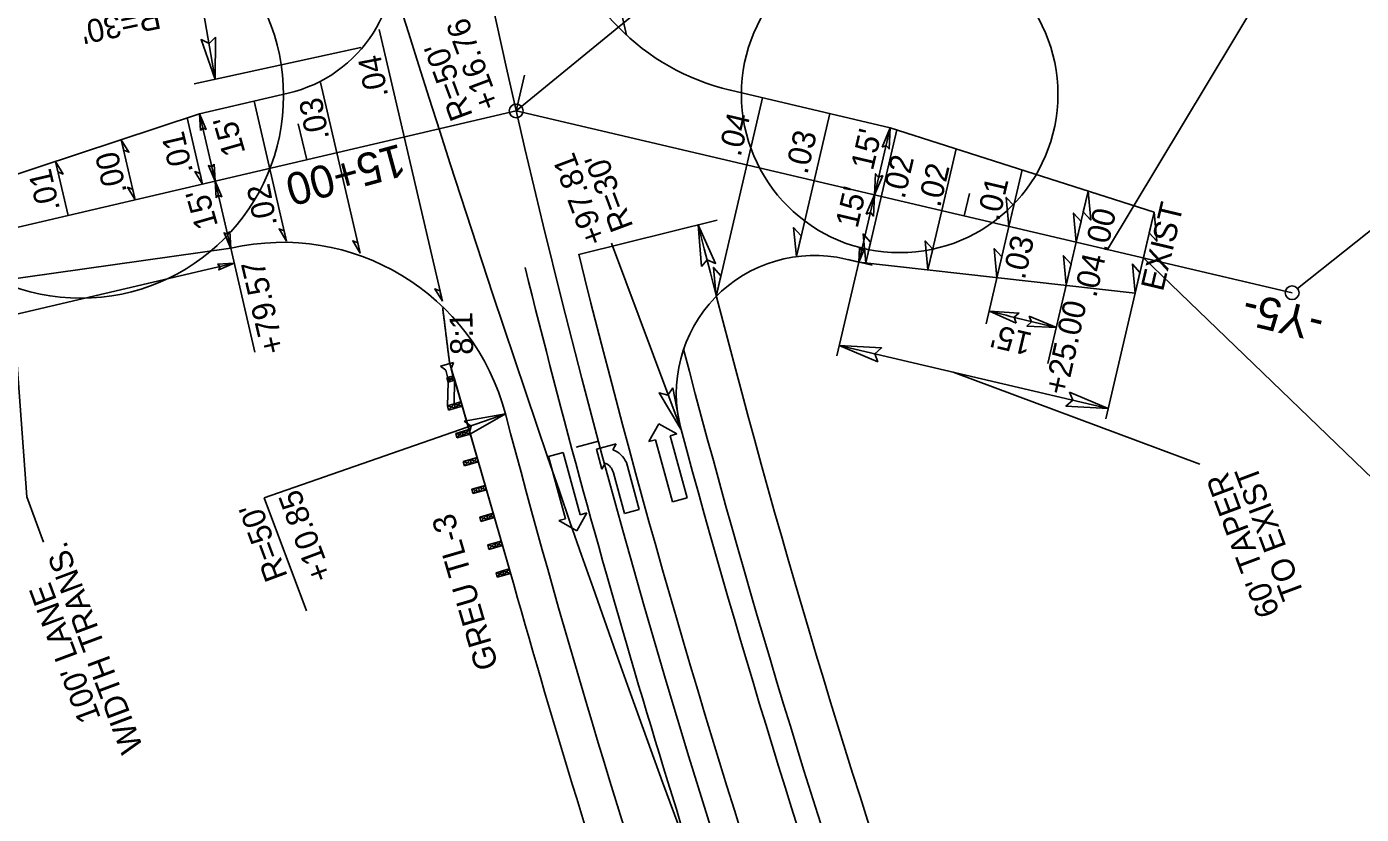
# Model space of a CAD drawing. Extents: x 472216 to 481979, y 489069 to 507339.
# Drawn here: x 478350.7 to 478640.7, y 494859.4 to 495030.5 of the extents above; entities that cross this region are included whole.
import ezdxf

# ---------------------------------------------------------------- set-up
doc = ezdxf.new("R2010")
doc.units = 0
for name, color, linetype in [('Old_Level_12', 7, 'Continuous'), ('Prop Drainage Structure Drop Inlet Grate 2 Narrow Slots and Sag Grates 840 24 CELL', 7, 'Continuous'), ('Prop Drainage Structure Drop Inlet Grate 2 Wide Slots and Sag Grates 840 22 Label', 7, 'Continuous'), ('Prop Drainage Structure Outlet Berm Ditch 850 10 CELL', 7, 'Continuous'), ('Prop Drainage Structure Pipe CSP 15in', 7, 'Continuous'), ('Prop Drainage Structure Pipe Plug CELL', 7, 'Continuous'), ('Prop Drainage Structure Pipe RCP 15in Class III Label', 7, 'Continuous'), ('Prop Drainage Structure Pipe RCP 24in Class III Label', 7, 'Continuous'), ('Prop Drainage Structure Pipe Side Drain 15in Label', 7, 'Continuous'), ('Prop Drainage Structure Tops and Inverts LABEL', 7, 'Continuous'), ('Prop Erosion Embankment Toe Protection CELL', 7, 'Continuous'), ('Sheet Block Revision CELL', 7, 'Continuous'), ('Sheet North Arrow Point CELL', 7, 'Continuous'), ('Sheet PE Seal Cell', 7, 'Continuous'), ('Sheet Plan And Profile CELL', 7, 'Continuous'), ('Sheet Plot Border Outside CELL', 7, 'Continuous'), ('Sheet Profile Grid Major CELL', 7, 'Continuous'), ('Sheet Profile Grid Minor CELL', 7, 'Continuous')]:
    doc.layers.add(name, color=color, linetype=linetype)

msp = doc.modelspace()

# ---------------------------------------------------------------- linework, layer by layer
at = {"layer": 'Old_Level_12'}
for p, q in [((478457.03, 495012.18), (478547.36, 495086.32)), ((478629.62, 495055.35), (478585.55, 494982.08)), ((478626.85, 494973.61), (478718.93, 495046.88)), ((478593.34, 494980.26), (478669.56, 494906.79))]:
    msp.add_line(p, q, dxfattribs=at)
for centre in [(478457.03, 495012.18), (478457.03, 495012.18), (478457.03, 495012.18), (478457.03, 495012.18), (478457.03, 495012.18), (478457.03, 495012.18), (478625.67, 494972.68), (478625.67, 494972.68)]:
    msp.add_circle(centre, 1.5, dxfattribs=at)
at = {"layer": 'Prop Drainage Structure Drop Inlet Grate 2 Narrow Slots and Sag Grates 840 24 CELL'}
for points in [[(478371.21, 495005.91), (478372.87, 495003.21), (478371.74, 495003.66)], [(478356.92, 495001.16), (478358.57, 494998.47), (478357.44, 494998.91)], [(478388.85, 494996.29), (478387.2, 494998.99), (478388.33, 494998.55)], [(478374.25, 494992.89), (478372.59, 494995.59), (478373.72, 494995.14)], [(478564.13, 494987.1), (478563.55, 494993.4), (478565.19, 494991.6)], [(478581.33, 494994.76), (478581.91, 494988.46), (478580.28, 494990.25)], [(478578.74, 494983.68), (478578.16, 494989.98), (478579.79, 494988.18)], [(478595.66, 494990.16), (478596.24, 494983.86), (478594.6, 494985.66)], [(478407.15, 494983.86), (478405.5, 494986.55), (478406.63, 494986.11)], [(478517.92, 494980.53), (478517.34, 494986.83), (478518.97, 494985.03)], [(478423.16, 494981.29), (478421.5, 494983.98), (478422.63, 494983.54)], [(478533, 494979.17), (478532.42, 494985.46), (478534.06, 494983.67)], [(478546.51, 494977.65), (478545.93, 494983.95), (478547.57, 494982.15)], [(478561.52, 494975.96), (478560.94, 494982.26), (478562.58, 494980.47)], [(478576.56, 494974.4), (478575.98, 494980.7), (478577.62, 494978.9)], [(478500.48, 494971.87), (478499.9, 494978.17), (478501.54, 494976.37)], [(478591.55, 494972.59), (478590.97, 494978.89), (478592.6, 494977.1)], [(478441, 494970.82), (478439.34, 494973.52), (478440.47, 494973.07)]]:
    msp.add_lwpolyline(points, close=True, dxfattribs=at)
at = {"layer": 'Prop Drainage Structure Drop Inlet Grate 2 Wide Slots and Sag Grates 840 22 Label'}
for p, q in [((478427.24, 495029.85), (478441, 494970.82)), ((478414.51, 495018.38), (478423.16, 494981.29)), ((478400.06, 495014.31), (478407.15, 494983.86)), ((478510.59, 495015.04), (478500.48, 494971.87)), ((478385.51, 495010.65), (478388.85, 494996.29)), ((478525.2, 495011.62), (478517.92, 494980.53)), ((478539.77, 495008.08), (478533, 494979.17)), ((478371.21, 495005.91), (478374.25, 494992.89)), ((478552.67, 495003.95), (478549.53, 494990.52)), ((478356.92, 495001.16), (478359.64, 494989.49)), ((478567, 494999.35), (478564.13, 494987.1)), ((478581.33, 494994.76), (478578.74, 494983.68)), ((478549.53, 494990.52), (478546.51, 494977.65)), ((478595.39, 494989.02), (478591.55, 494972.59)), ((478559.16, 494965.89), (478564.13, 494987.1)), ((478578.74, 494983.68), (478576.56, 494974.4)), ((478576.83, 494975.55), (478572.55, 494957.27))]:
    msp.add_line(p, q, dxfattribs=at)
for points in [[(478565.73, 494966.1), (478559.87, 494968.67), (478566.29, 494968.24), (478565.24, 494967.34)], [(478568.54, 494967.58), (478574.45, 494965.15), (478568.02, 494965.43), (478569.05, 494966.35)]]:
    msp.add_lwpolyline(points, close=True, dxfattribs=at)
msp.add_arc((478781.06, 495851.38), 910, 255.9328, 256.87377, dxfattribs=at)
at = {"layer": 'Prop Drainage Structure Outlet Berm Ditch 850 10 CELL'}
for points in [[(478391.65, 495028.17), (478391.62, 495019.03), (478388.54, 495027.69), (478390.3, 495026.82)], [(478388.41, 495007.9), (478388.2, 495011.54), (478389.64, 495008.16), (478388.92, 495008.47)], [(478536.56, 495004.32), (478538.34, 495008.53), (478538.09, 495003.94), (478537.44, 495004.68)], [(478391.37, 495000.58), (478391.59, 494996.93), (478390.14, 495000.31), (478390.87, 495000.01)], [(478536.69, 494998.13), (478534.91, 494993.93), (478535.16, 494998.52), (478535.81, 494997.77)], [(478391.8, 494993.28), (478391.59, 494996.93), (478393.03, 494993.55), (478392.3, 494993.85)], [(478533.13, 494989.72), (478534.91, 494993.93), (478534.66, 494989.34), (478534.01, 494990.08)], [(478497.3, 494978.35), (478496.62, 494987.45), (478500.37, 494979.06), (478498.54, 494979.79)], [(478394.78, 494985.97), (478394.99, 494982.32), (478393.54, 494985.7), (478394.27, 494985.4)], [(478532.71, 494982.19), (478531.5, 494979.32), (478531.67, 494982.45), (478532.11, 494981.94)], [(478392.12, 494978.86), (478395.76, 494979.07), (478392.38, 494977.62), (478392.69, 494978.35)], [(478535.66, 494957.64), (478527.26, 494961.21), (478536.43, 494960.69), (478534.95, 494959.4)], [(478491.05, 494951.99), (478492.85, 494943.04), (478488.09, 494950.9), (478490, 494950.41)], [(478577.27, 494951.1), (478585.68, 494947.53), (478576.5, 494948.05), (478577.99, 494949.34)], [(478445.71, 494944.8), (478454.71, 494946.34), (478446.71, 494941.81), (478447.26, 494943.7)]]:
    msp.add_lwpolyline(points, close=True, dxfattribs=at)
at = {"layer": 'Prop Drainage Structure Pipe Plug CELL'}
for p, q in [((478443.43, 494957.51), (478440.59, 494956.75)), ((478442.91, 494956.16), (478443.43, 494957.51)), ((478440.59, 494956.75), (478441.73, 494955.84)), ((478441.73, 494955.84), (478442.26, 494953.86)), ((478443.38, 494954.65), (478441.94, 494954.23)), ((478442.22, 494953.27), (478441.94, 494954.23)), ((478441.94, 494954.23), (478443.66, 494953.69)), ((478443.38, 494954.65), (478442.22, 494953.27)), ((478442.85, 494954.02), (478443.44, 494954.18)), ((478443.44, 494954.18), (478442.91, 494956.16)), ((478456.51, 494909.26), (478443.52, 494954.17)), ((478442.22, 494953.27), (478442.08, 494953.75)), ((478442.08, 494948.13), (478442.22, 494953.27)), ((478443.66, 494953.69), (478442.22, 494953.27)), ((478442.26, 494953.86), (478442.85, 494954.02)), ((478443.55, 494948.56), (478443.66, 494953.69)), ((478445.02, 494948.98), (478442.08, 494948.13)), ((478443.55, 494948.56), (478442.36, 494947.17)), ((478443.83, 494947.59), (478443.55, 494948.56)), ((478445.3, 494948.02), (478443.55, 494948.56)), ((478443.83, 494947.59), (478445.02, 494948.98)), ((478442.36, 494947.17), (478442.08, 494948.13)), ((478442.08, 494948.13), (478443.83, 494947.59)), ((478445.3, 494948.02), (478442.36, 494947.17)), ((478446.77, 494942.93), (478443.89, 494942.09)), ((478445.61, 494941.55), (478446.77, 494942.93)), ((478444.17, 494941.13), (478443.89, 494942.09)), ((478443.89, 494942.09), (478445.61, 494941.55)), ((478445.33, 494942.51), (478444.17, 494941.13)), ((478447.05, 494941.97), (478444.17, 494941.13)), ((478445.61, 494941.55), (478445.33, 494942.51)), ((478447.05, 494941.97), (478445.33, 494942.51)), ((478448.52, 494936.87), (478445.51, 494936)), ((478447.29, 494935.48), (478448.52, 494936.87)), ((478445.79, 494935.04), (478445.51, 494936)), ((478445.51, 494936), (478447.29, 494935.48)), ((478447.02, 494936.44), (478445.79, 494935.04)), ((478448.8, 494935.91), (478445.79, 494935.04)), ((478447.29, 494935.48), (478447.02, 494936.44)), ((478448.8, 494935.91), (478447.02, 494936.44)), ((478450.27, 494930.82), (478447.36, 494929.98)), ((478447.64, 494929.02), (478447.36, 494929.98)), ((478447.36, 494929.98), (478449.09, 494929.44)), ((478448.82, 494930.4), (478447.64, 494929.02)), ((478450.55, 494929.86), (478447.64, 494929.02)), ((478449.09, 494929.44), (478448.82, 494930.4)), ((478450.55, 494929.86), (478448.82, 494930.4)), ((478449.09, 494929.44), (478450.27, 494930.82)), ((478450.55, 494929.86), (478450.27, 494930.82)), ((478452.03, 494924.77), (478449.1, 494923.92)), ((478449.38, 494922.96), (478449.1, 494923.92)), ((478449.1, 494923.92), (478450.84, 494923.38)), ((478450.56, 494924.35), (478449.38, 494922.96)), ((478452.3, 494923.81), (478449.38, 494922.96)), ((478450.84, 494923.38), (478450.56, 494924.35)), ((478452.3, 494923.81), (478450.56, 494924.35)), ((478450.84, 494923.38), (478452.03, 494924.77)), ((478453.78, 494918.72), (478450.84, 494917.87)), ((478451.12, 494916.91), (478450.84, 494917.87)), ((478450.84, 494917.87), (478452.59, 494917.33)), ((478452.31, 494918.29), (478451.12, 494916.91)), ((478454.05, 494917.75), (478451.12, 494916.91)), ((478452.59, 494917.33), (478452.31, 494918.29)), ((478454.05, 494917.75), (478452.31, 494918.29)), ((478452.59, 494917.33), (478453.78, 494918.72)), ((478455.53, 494912.66), (478452.65, 494911.83)), ((478452.92, 494910.87), (478452.65, 494911.83)), ((478452.65, 494911.83), (478454.36, 494911.28)), ((478454.09, 494912.25), (478452.92, 494910.87)), ((478455.81, 494911.7), (478452.92, 494910.87)), ((478455.53, 494912.66), (478454.09, 494912.25)), ((478454.36, 494911.28), (478454.09, 494912.25)), ((478454.09, 494912.25), (478455.81, 494911.7)), ((478454.36, 494911.28), (478455.53, 494912.66)), ((478455.81, 494911.7), (478455.53, 494912.66))]:
    msp.add_line(p, q, dxfattribs=at)
at = {"layer": 'Prop Drainage Structure Pipe RCP 15in Class III Label'}
for radius, end in [(2044, 203.67633), (2056, 199.48395)]:
    msp.add_arc((480454.83, 495471.85), radius, 193.89422, end, dxfattribs=at)
at = {"layer": 'Prop Drainage Structure Pipe RCP 24in Class III Label'}
for p, q in [((478388.2, 495011.54), (478407.47, 495016.03)), ((478538.34, 495008.54), (478502.41, 495016.96)), ((478388.2, 495011.54), (478292.81, 494980.1)), ((478595.66, 494990.16), (478538.34, 495008.54)), ((478595.66, 494990.16), (478591.55, 494972.59)), ((478395.01, 494982.33), (478295.31, 494968.37)), ((478528.67, 494980), (478531.5, 494979.33)), ((478531.5, 494979.33), (478591.55, 494972.59))]:
    msp.add_line(p, q, dxfattribs=at)
for centre, radius, start, end in [((478514.96, 495065.37), 50, 191.8344, 256.8192), ((478400.66, 495045.25), 30, 283.1168, 11.732), ((478406.35, 494933.63), 50, 14.7212, 103.1168), ((478521.83, 494950.79), 30, 76.8192, 195.0861), ((480454.83, 495471.85), 2068, 194.72116, 202.46558), ((480454.83, 495471.85), 2032, 195.08605, 203.67633)]:
    msp.add_arc(centre, radius, start, end, dxfattribs=at)
at = {"layer": 'Prop Drainage Structure Pipe Side Drain 15in Label'}
for p, q in [((478485.89, 494940.34), (478488.05, 494944.2)), ((478488.05, 494944.2), (478491.97, 494942)), ((478478.78, 494939.83), (478474.52, 494938.72)), ((478478.04, 494938.54), (478478.78, 494939.83)), ((478487.34, 494940.74), (478485.89, 494940.34)), ((478491.03, 494927.23), (478487.34, 494940.74)), ((478491.97, 494942), (478490.52, 494941.61)), ((478490.52, 494941.61), (478494.22, 494928.1)), ((478464.06, 494937.06), (478467.25, 494937.93)), ((478467.75, 494923.55), (478464.06, 494937.06)), ((478467.25, 494937.93), (478470.94, 494924.42)), ((478474.52, 494938.72), (478475.66, 494934.37)), ((478475.66, 494934.37), (478476.39, 494935.66)), ((478483.76, 494925.59), (478480.98, 494935.77)), ((478478.16, 494933.55), (478480.58, 494924.72)), ((478494.22, 494928.1), (478491.03, 494927.23)), ((478480.58, 494924.72), (478483.76, 494925.59)), ((478466.31, 494923.16), (478467.75, 494923.55)), ((478470.23, 494920.96), (478466.31, 494923.16)), ((478472.38, 494924.82), (478470.23, 494920.96)), ((478470.94, 494924.42), (478472.38, 494924.82))]:
    msp.add_line(p, q, dxfattribs=at)
for centre, radius, start, end in [((478476.19, 494933.64), 5.25, 23.9678, 69.2795), ((478475.02, 494932.7), 3.27, 15.2917, 64.9499)]:
    msp.add_arc(centre, radius, start, end, dxfattribs=at)
at = {"layer": 'Prop Drainage Structure Tops and Inverts LABEL'}
msp.add_arc((480454.83, 495471.85), 2076, 195.72355, 201.07088, dxfattribs=at)
at = {"layer": 'Prop Erosion Embankment Toe Protection CELL'}
for p, q in [((478467.99, 495085.8), (478481.04, 495028.64)), ((478456.51, 494909.26), (478442.58, 494957.29))]:
    msp.add_line(p, q, dxfattribs=at)
for radius, start, end in [(2027, 194.61439, 203.67633), (2076, 195.72355, 201.07088)]:
    msp.add_arc((480454.83, 495471.85), radius, start, end, dxfattribs=at)
msp.add_spline([(478442.58, 494957.28), (478442.52, 494957.72), (478442.47, 494958.16), (478442.41, 494958.59), (478442.35, 494959.03), (478442.3, 494959.47), (478442.24, 494959.91), (478442.19, 494960.35), (478442.13, 494960.78), (478442.08, 494961.22), (478442.02, 494961.66), (478441.97, 494962.1), (478441.91, 494962.54), (478441.86, 494962.97), (478441.8, 494963.41), (478441.75, 494963.85), (478441.69, 494964.29), (478441.64, 494964.72), (478441.58, 494965.16), (478441.53, 494965.6), (478441.47, 494966.04), (478441.42, 494966.48), (478441.37, 494966.91), (478441.31, 494967.35), (478441.26, 494967.79), (478441.2, 494968.23), (478441.15, 494968.67), (478441.1, 494969.1), (478441.05, 494969.49)], degree=3, dxfattribs=at)
at = {"layer": 'Sheet Block Revision CELL'}
for p, q in [((478391.62, 495019.03), (478331.63, 495366.81)), ((478423.27, 495025.98), (478387.04, 495018.03)), ((478394.99, 494982.32), (478388.2, 495011.54)), ((478531.5, 494979.32), (478538.34, 495008.53)), ((478470.63, 494981.02), (478500.73, 494988.47)), ((478492.86, 494942.98), (478477.75, 494983.45)), ((478395.01, 494982.33), (478400.26, 494959.78)), ((478297.68, 494956.21), (478395.76, 494979.07)), ((478526.73, 494958.95), (478531.5, 494979.33)), ((478529.15, 494979.87), (478534.41, 494978.64)), ((478591.55, 494972.59), (478585.15, 494945.27)), ((478350.65, 494928.32), (478347.79, 494967.89)), ((478527.26, 494961.21), (478527.26, 494961.21)), ((478527.26, 494961.21), (478585.68, 494947.53)), ((478551.98, 494955.42), (478605.59, 494935.4)), ((478454.71, 494946.34), (478402.26, 494928.14)), ((478354.32, 494918.48), (478350.65, 494928.32)), ((478402.26, 494928.14), (478411.44, 494903.55))]:
    msp.add_line(p, q, dxfattribs=at)
msp.add_arc((480463.68, 495476.73), 2027, 193.96805, 203.70226, dxfattribs=at)
at = {"layer": 'Sheet North Arrow Point CELL'}
for p, q in [((478296.05, 494974.67), (478457.03, 495012.18)), ((478457.03, 495012.18), (478625.67, 494972.68))]:
    msp.add_line(p, q, dxfattribs=at)
for centre, radius, start, end in [((481983.35, 496141.85), 3720, 188.99254, 203.7418), ((480454.83, 495471.85), 2050, 189.81618, 250.32977)]:
    msp.add_arc(centre, radius, start, end, dxfattribs=at)
at = {"layer": 'Sheet PE Seal Cell'}
for p, q in [((478554.39, 494989.38), (478555.53, 494994.25)), ((478554.39, 494989.38), (478555.53, 494994.25)), ((478474.91, 494940.43), (478470.08, 494939.13))]:
    msp.add_line(p, q, dxfattribs=at)
at = {"layer": 'Sheet Plot Border Outside CELL'}
for centre, radius in [((478362.44, 495015.53), 44.04), ((478540.38, 495015.78), 34.39)]:
    msp.add_circle(centre, radius, dxfattribs=at)
at = {"layer": 'Sheet Profile Grid Minor CELL'}
for p, q in [((478457.03, 495012.18), (478458.85, 495019.97)), ((478457.03, 495012.18), (478458.85, 495019.97)), ((478411.5, 495001.57), (478409.68, 495009.36))]:
    msp.add_line(p, q, dxfattribs=at)

# ---------------------------------------------------------------- texts
at = {"layer": 'Prop Drainage Structure Drop Inlet Grate 2 Narrow Slots and Sag Grates 840 24 CELL'}
for s, rotation, p in [('.04', 76.8192, (478505.79, 495002.05)), ('.03', 76.8192, (478520.3, 494998.21)), ('.02', 76.8192, (478541.42, 494992.88)), ('.02', 76.8192, (478549.16, 494991.05)), ('.01', 76.8192, (478561.96, 494988.07)), ('EXIST', 76.57, (478597.59, 494972.78)), ('.00', 76.8192, (478585.37, 494981.29)), ('.03', 76.8192, (478567.54, 494975.36)), ('.04', 76.8192, (478583.06, 494971.45))]:
    msp.add_text(s, height=5, rotation=rotation, dxfattribs=at).set_placement(p)
at = {"layer": 'Prop Drainage Structure Drop Inlet Grate 2 Wide Slots and Sag Grates 840 22 Label'}
for s, rotation, p in [('.04', 100.8426, (478429.24, 495015.48)), ('.03', 100.8426, (478416.43, 495006.26)), ('.01', 103.1168, (478386.83, 494999)), ('.00', 103.1168, (478372.45, 494994.64)), ('.01', 103.1168, (478357.93, 494990.86)), ('.02', 100.8426, (478405.1, 494987.51)), ('+25.00', 77.4629, (478576.58, 494950.19)), ("15'", 166.7844, (478569.44, 494963.84))]:
    msp.add_text(s, height=5, rotation=rotation, dxfattribs=at).set_placement(p)
at = {"layer": 'Prop Drainage Structure Pipe CSP 15in'}
for s, rotation, p in [("R=30'", 191.718, (478379.14, 495035.07)), ('+16.76', 110.469, (478453.58, 495013.47)), ("R=50'", 110.469, (478447.66, 495011.22)), ("15'", 106.0521, (478398.23, 495003.17)), ("15'", 76.8192, (478534.55, 494999.05)), ('+97.81', 110.469, (478476.72, 494984.13)), ("R=30'", 110.469, (478482.53, 494987.07)), ("15'", 76.8192, (478531.21, 494986.5)), ("15'", 106.0521, (478392.29, 494987.26)), ('+79.57', 103.2642, (478406.77, 494960.02)), ('8:1', 91.3984, (478447.73, 494959.25)), ('TO EXIST', 110.469, (478628.39, 494907.04)), ("60' TAPER", 110.469, (478623.04, 494903.24)), ('+10.85', 110.469, (478417.11, 494910.95)), ("R=50'", 110.4719, (478407.42, 494911.09)), ('WIDTH TRANS.', 110.469, (478376.03, 494873.75)), ("100' LANE ", 110.469, (478366.82, 494880.29))]:
    msp.add_text(s, height=5, rotation=rotation, dxfattribs=at).set_placement(p)
at = {"layer": 'Prop Drainage Structure Pipe Plug CELL'}
msp.add_text('GREU TL-3', height=5, rotation=106.2763, dxfattribs=at).set_placement((478453.2, 494891.52))
at = {"layer": 'Sheet Plan And Profile CELL'}
msp.add_text('-Y5-', height=7, rotation=166.57, dxfattribs=at).set_placement((478633.04, 494968.73))
at = {"layer": 'Sheet Profile Grid Major CELL'}
msp.add_text('15+00', height=7, rotation=195.2853, dxfattribs=at).set_placement((478431.74, 495005.09))

doc.saveas('drawing.dxf')
